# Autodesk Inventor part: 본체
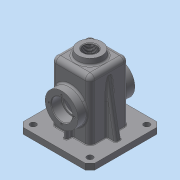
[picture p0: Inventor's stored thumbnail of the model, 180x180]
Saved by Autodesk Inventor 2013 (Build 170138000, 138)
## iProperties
Created: 2018-10
Part Number: 본체
Material: 일반
Document SubType Name: Modeling
Designer: Administrator
Density: 1 g/cm^3
Author: Administrator
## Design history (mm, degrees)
sketch "스케치1"
  geometry: L1 (-32.5, 32.5)-(32.5, 32.5); L2 (32.5, 32.5)-(32.5, -32.5); L3 (32.5, -32.5)-(-32.5, -32.5); L4 (-32.5, -32.5)-(-32.5, 32.5); L5 (-32.5, 32.5)-(32.5, -32.5); L6 (32.5, 32.5)-(-32.5, -32.5); 1 further point
  constraints: 12 end point, 2 midpoint, 2 parallel, 1 horizontal, 1 perpendicular
  dimensions: "d0" = 65 distance of L2.end L3.end; "d1" = 65 distance of L1.end L2.end
extrude "돌출1" new body sketch "스케치1" distance "d2" = 110; taper "d3" = 0 deg
sketch "스케치2"
  geometry: L1 (-27.5, 27.5)-(27.5, 27.5); L2 (27.5, 27.5)-(27.5, -27.5); L3 (27.5, -27.5)-(-27.5, -27.5); L4 (-27.5, -27.5)-(-27.5, 27.5); L5 (-27.5, 27.5)-(27.5, -27.5); L6 (27.5, 27.5)-(-27.5, -27.5); 1 further point
  constraints: 12 end point, 2 midpoint, 2 parallel, 1 horizontal, 1 perpendicular
  dimensions: "d4" = 55 distance of L2.end L3.end; "d5" = 55 distance of L1.end L2.end
extrude "돌출2" cut sketch "스케치2" distance "d6" = 105; taper "d7" = 0 deg
sketch "스케치3"
  geometry: L1 (32.5, 32.5)-(-32.5, 32.5) reference; L2 (-32.5, 32.5)-(-32.5, -32.5) reference; L3 (-32.5, -32.5)-(32.5, -32.5) reference; L4 (32.5, -32.5)-(32.5, 32.5) reference; L5 (-60, 60)-(60, 60); L6 (60, 60)-(60, -60); L7 (60, -60)-(-60, -60); L8 (-60, -60)-(-60, 60); L9 (-60, 60)-(60, -60); L10 (60, 60)-(-60, -60); 1 further point
  constraints: 12 end point, 2 midpoint, 2 parallel, 1 horizontal, 1 perpendicular
  dimensions: "d8" = 120 distance of L6.end L7.end; "d9" = 120 distance of L5.end L6.end
extrude "돌출3" join sketch "스케치3" distance "d10" = 10; taper "d11" = 0 deg
sketch "스케치4"
  geometry: L1 (27.5, 0)-(27.5, 105) reference; L2 (27.5, 105)-(-27.5, 105) reference; L3 (-27.5, 105)-(-27.5, 0) reference; L4 (-27.5, 0)-(-60, 0) reference; L5 (-60, 0)-(-60, 10) reference; L6 (-60, 10)-(-32.5, 10) reference; L7 (-32.5, 10)-(-32.5, 110) reference; L8 (-32.5, 110)-(32.5, 110) reference; L9 (32.5, 110)-(32.5, 10) reference; L10 (32.5, 10)-(60, 10) reference; L11 (60, 10)-(60, 0) reference; L12 (60, 0)-(27.5, 0) reference; L13 (-84, 0)-(84, 0) reference; L14 (0, -26)-(0, 156) reference; L15 (0, 110)-(0, 120); L16 (0, 120)-(20, 120); L17 (20, 120)-(21.228, 110); L18 (20, 120)-(35, 120); L19 (21.228, 110)-(0, 110); 1 further point
  constraints: 10 end point, 3 point on line, 2 perpendicular, 1 horizontal, 1 midpoint
  dimensions: "d13" = 10 distance of L15.start L15.end; "d14" = 20 distance of L15.end L16.end; "d16" = 83 deg angle of L17 L18
revolve "회전1" sketch "스케치4" stored, may be unused: angle "d17" = 90 deg
sketch "스케치5"
  geometry: L1 (92.5, -100)-(92.5, -110) reference; L2 (92.5, -110)-(-27.5, -110) reference; L3 (-27.5, -110)-(-27.5, -100) reference; L4 (-27.5, -100)-(0, -100) reference; L5 (0, -100)-(65, -100) reference; L6 (65, -100)-(92.5, -100) reference; L7 (0, -100)-(0, 0) reference; L8 (0, 0)-(65, 0) reference; L9 (65, 0)-(65, -100) reference; L10 (32.5, -144)-(32.5, 24) reference; L11 (-51.5, -110)-(116.5, -110) reference; C1 r 27.5 at (32.5, -55); 1 further point
  constraints: 1 centre point, 1 point on line
  dimensions: "d18" = 55 diameter of C1; "d19" = 55 distance from line of L2 C1.centre
extrude "돌출4" join sketch "스케치5" distance "d20" = 15; taper "d21" = 0 deg
sketch "스케치6"
  geometry: C1 r 27.5 at (0, 0) reference; C2 r 17.5 at (0, 0); 1 further point
  constraints: 1 centre point, 1 coincident
  dimensions: "d22" = 35 diameter of C2
extrude "돌출5" cut sketch "스케치6" distance "d23" = 17; taper "d24" = 0 deg
sketch "스케치7"
  geometry: C1 r 17.5 at (0, 0) reference; C2 r 15 at (0, 0); 1 further point
  constraints: 1 centre point, 1 coincident
  dimensions: "d25" = 30 diameter of C2
extrude "돌출6" cut sketch "스케치7" distance "d26" = 3; taper "d27" = 0 deg
sketch "스케치8" dims "d28" = 42
  geometry: L1 (0, 0)-(0, 21); C1 r 27.5 at (0, 0) reference; 1 further point
  constraints: 2 end point, 1 coincident, 1 vertical, 1 vertical alignment, 2 other
hole "구멍1" sketch "스케치8" at (0, 21) diameter "d29" = 3.242; stored, may be unused: countersink angle "d33" = 90 deg, drill point angle "d35" = 118 deg; dims "d30" = 8, "d31" = 4, "d32" = 2, "d34" = 10
sketch "스케치9"
  geometry: L1 (27.5, 0)-(27.5, 105) reference; L2 (27.5, 105)-(-27.5, 105) reference; L3 (-27.5, 105)-(-27.5, 0) reference; L4 (-27.5, 0)-(-60, 0) reference; L5 (-60, 0)-(-60, 10) reference; L6 (-60, 10)-(-32.5, 10) reference; L7 (-32.5, 10)-(-32.5, 110) reference; L8 (-32.5, 110)-(-21.228, 110) reference; L9 (-21.228, 110)-(-20, 120) reference; L10 (-20, 120)-(20, 120) reference; L11 (20, 120)-(21.228, 110) reference; L12 (21.228, 110)-(32.5, 110) reference; L13 (32.5, 110)-(32.5, 10) reference; L14 (32.5, 10)-(60, 10) reference; L15 (60, 10)-(60, 0) reference; L16 (60, 0)-(27.5, 0) reference; L17 (-84, 0)-(84, 0) reference; L18 (0, -24)-(0, 144) reference; L19 (48, 10)-(32.5, 97.905); 1 further point
  constraints: 2 end point, 2 point on line
  dimensions: "d39" = 12 distance from line of L15 L19.start; "d40" = 10 deg angle of L19 L15
feature "리브1" sketch "스케치9" dims "d41" = 1, "d42" = 10, "d43" = 0, "d44" = 0, "d45" = 1, "d46" = 1
hole "구멍2" diameter "d49" = 22.835; stored, may be unused: countersink angle "d53" = 90 deg, drill point angle "d55" = 118 deg; dims "d47" = 10, "d48" = 10, "d50" = 100, "d51" = 4, "d52" = 2, "d54" = 10
fillet "모깎기1" dims "d56" = 8
fillet "모깎기2" dims "d57" = 8
fillet "모깎기3" dims "d58" = 8
fillet "모깎기4" dims "d59" = 3
chamfer "모따기1" distance "d60" = 1; stored, may be unused: second distance "d61" = 2, angle "d62" = 45 deg
chamfer "모따기2" distance "d63" = 1; stored, may be unused: second distance "d64" = 2, angle "d65" = 45 deg
sketch "스케치10"
  geometry: L1 (70, -30.5)-(70, -27.5) reference; L2 (70, -27.5)-(105, -27.5) reference; L3 (105, -27.5)-(105, -11.418) reference; L4 (105, -11.418)-(119, -11.418) reference; L5 (119, -11.418)-(120, -12.418) reference; L6 (120, -12.418)-(120, -20) reference; L7 (120, -20)-(112.634, -20.904) reference; L8 (110, -23.882)-(110, -24.5) reference; L9 (102, -32.5)-(82.5, -32.5) reference; L10 (82.5, -32.5)-(82.5, -47.5) reference; L11 (82.5, -47.5)-(77.621, -47.5) reference; L12 (77.621, -47.5)-(77.621, -37.5) reference; L13 (77.621, -37.5)-(76, -36.526) reference; L14 (76, -36.526)-(74.379, -37.5) reference; L15 (74.379, -37.5)-(74.379, -47.5) reference; L16 (74.379, -47.5)-(73.5, -47.5) reference; L17 (73.5, -47.5)-(72.5, -46.5) reference; L18 (72.5, -46.5)-(72.5, -30.5) reference; L19 (72.5, -30.5)-(70, -30.5) reference; L20 (40, -27.5)-(40, -30.5) reference; L21 (40, -30.5)-(37.5, -30.5) reference; L22 (37.5, -30.5)-(37.5, -46.5) reference; L23 (37.5, -46.5)-(36.5, -47.5) reference; L24 (36.5, -47.5)-(35.621, -47.5) reference; L25 (35.621, -47.5)-(35.621, -37.5) reference; L26 (35.621, -37.5)-(34, -36.526) reference; L27 (34, -36.526)-(32.379, -37.5) reference; L28 (32.379, -37.5)-(32.379, -47.5) reference; L29 (32.379, -47.5)-(27.5, -47.5) reference; L30 (27.5, -47.5)-(27.5, -32.5) reference; L31 (27.5, -32.5)-(10, -32.5) reference; L32 (10, -32.5)-(10, -60) reference; L33 (10, -60)-(0, -60) reference; L34 (0, -60)-(0, -27.5) reference; L35 (0, -27.5)-(40, -27.5) reference; L36 (70, 27.5)-(70, 30.5) reference; L37 (70, 30.5)-(72.5, 30.5) reference; L38 (72.5, 30.5)-(72.5, 46.5) reference; L39 (72.5, 46.5)-(73.5, 47.5) reference; L40 (73.5, 47.5)-(74.379, 47.5) reference; L41 (74.379, 47.5)-(74.379, 37.5) reference; L42 (74.379, 37.5)-(76, 36.526) reference; L43 (76, 36.526)-(77.621, 37.5) reference; L44 (77.621, 37.5)-(77.621, 47.5) reference; L45 (77.621, 47.5)-(82.5, 47.5) reference; L46 (82.5, 47.5)-(82.5, 32.5) reference; L47 (82.5, 32.5)-(102, 32.5) reference; L48 (110, 24.5)-(110, 23.882) reference; L49 (112.634, 20.904)-(120, 20) reference; L50 (120, 20)-(120, 12.418) reference; L51 (120, 12.418)-(119, 11.418) reference; L52 (119, 11.418)-(105, 11.418) reference; L53 (105, 11.418)-(105, 27.5) reference; L54 (105, 27.5)-(70, 27.5) reference; L55 (40, 30.5)-(40, 27.5) reference; L56 (40, 27.5)-(0, 27.5) reference; L57 (0, 27.5)-(0, 60) reference; L58 (0, 60)-(10, 60) reference; L59 (10, 60)-(10, 32.5) reference; L60 (10, 32.5)-(27.5, 32.5) reference; L61 (27.5, 32.5)-(27.5, 47.5) reference; L62 (27.5, 47.5)-(32.379, 47.5) reference; L63 (32.379, 47.5)-(32.379, 37.5) reference; L64 (32.379, 37.5)-(34, 36.526) reference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; A1 r 3 centre (113, -23.882) between (112.634, -20.904) and (110, -23.882) reference; A2 r 8 centre (102, -24.5) between (102, -32.5) and (110, -24.5) reference; A3 r 8 centre (102, 24.5) between (110, 24.5) and (102, 32.5) reference; A4 r 3 centre (113, 23.882) between (110, 23.882) and (112.634, 20.904) reference; 1 further point
  constraints: 2 end point, 2 point on line, 1 perpendicular
  dimensions: "d66" = 15 distance between parallel lines of L73 L56
feature "리브2" sketch "스케치10" dims "d68" = 1, "d69" = 6, "d70" = 0, "d71" = 0, "d72" = 1, "d73" = 1
sketch "스케치11"
  geometry: L1 (-47.5, 47.5)-(47.5, 47.5); L2 (47.5, 47.5)-(47.5, -47.5); L3 (47.5, -47.5)-(-47.5, -47.5); L4 (-47.5, -47.5)-(-47.5, 47.5); L5 (-47.5, 47.5)-(47.5, -47.5); L6 (47.5, 47.5)-(-47.5, -47.5); 1 further point
  constraints: 12 end point, 2 midpoint, 2 parallel, 1 horizontal, 1 perpendicular
  dimensions: "d74" = 95 distance of L2.end L3.end; "d75" = 95 distance of L1.end L2.end
hole "구멍3" sketch "스케치11" at (-47.5, 47.5) diameter "d76" = 10; stored, may be unused: countersink angle "d80" = 90 deg, drill point angle "d82" = 118 deg; dims "d77" = 6, "d78" = 4, "d79" = 2, "d81" = 8
chamfer "모따기3" distance "d83" = 8; stored, may be unused: second distance "d84" = 2, angle "d85" = 45 deg
fillet "모깎기5" dims "d86" = 3
fillet "모깎기6" dims "d87" = 3
fillet "모깎기7" dims "d88" = 3
fillet "모깎기8" dims "d89" = 3
fillet "모깎기9" dims "d90" = 3
fillet "모깎기10" dims "d91" = 3
fillet "모깎기11" dims "d92" = 3
fillet "모깎기12" dims "d93" = 1
sketch "스케치12"
  geometry: L1 (-8, 0)-(-8, -91) reference; L2 (4.5, 18)-(44.5, 18) reference; 2 further points
  constraints: 1 other
  dimensions: "d94" = 32.5 distance from line of L1 point (24.5, -8); "d95" = 26 distance from line of L2 point (24.5, -8)
feature "엠보싱1" sketch "스케치12" dims "d96" = 0.5, "d97" = 0
fillet "모깎기13" dims "d98" = 3
fillet "모깎기14" dims "d99" = 3
fillet "모깎기15" dims "d100" = 0.3
node "솔리드1"
mirror "대칭1"
mirror "대칭2"
mirror "대칭3"
pattern_circular "원형 패턴1" dims angle "d37" = 360 deg
mirror "대칭4"
mirror "대칭5"
mirror "대칭6"
mirror "대칭7"
mirror "대칭8"
node "절단 모서리 투영1"
node "절단 모서리 투영2"
node "절단 모서리 투영3"
node "절단 모서리 투영4"
